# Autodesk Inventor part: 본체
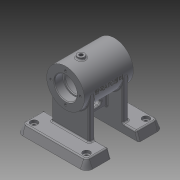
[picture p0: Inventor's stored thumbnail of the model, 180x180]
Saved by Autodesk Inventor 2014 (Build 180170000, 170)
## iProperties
Created: 2016-07
Part Number: 본체
Material: 일반
Document SubType Name: Modeling
Designer: USER
Density: 1 g/cm^3
Appearance: 기본값
Author: USER
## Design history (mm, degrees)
sketch "스케치1"
  geometry: L1 (0, 0)-(100, 0); L2 (100, 0)-(100, 110); L3 (100, 110)-(0, 110); L4 (0, 110)-(0, 0)
  constraints: 8 end point, 1 horizontal, 1 parallel, 1 perpendicular
  dimensions: "d0" = 100 distance of L1.start L1.end; "d1" = 110 distance of L1.end L2.end; "d2" = 100 distance of L2.end L3.end
extrude "돌출1" new body sketch "스케치1" distance "d3" = 12; taper "d4" = -20 deg
sketch "스케치2"
  geometry: L1 (4.368, 4.368)-(4.368, 105.632) reference; L2 (95.632, 105.632)-(95.632, 4.368) reference; L3 (4.368, 105.632)-(95.632, 105.632) reference; L4 (-24.368, 35)-(125.632, 35); L5 (125.632, 35)-(125.632, 75); L6 (125.632, 75)-(-24.368, 75); L7 (-24.368, 75)-(-24.368, 35); 3 further points
  constraints: 8 end point, 3 perpendicular, 2 midpoint, 1 horizontal alignment, 1 parallel
  dimensions: "d5" = 40 distance of L4.end L5.end; "d6" = 150 distance of L5.end L6.end; "d7" = 30 distance between parallel lines of L2 L5
extrude "돌출2" cut sketch "스케치2" distance "d8" = 12; taper "d9" = 0 deg
sketch "스케치3"
  geometry: L1 (95.632, 35)-(4.368, 35) reference; L2 (95.632, 4.368)-(4.368, 4.368) reference; L3 (4.368, 75)-(95.632, 75) reference; L4 (95.632, 105.632)-(95.632, 75) reference; L5 (4.368, 105.632)-(95.632, 105.632) reference; L6 (4.368, 75)-(4.368, 105.632) reference; L7 (23, 35)-(23, 27); L8 (23, 27)-(77, 27); L9 (77, 27)-(77, 35); L10 (23, 35)-(77, 35); L11 (23, 75)-(23, 83); L12 (23, 83)-(77, 83); L13 (77, 83)-(77, 75); L14 (23, 75)-(77, 75); 5 further points
  constraints: 16 end point, 4 midpoint, 4 perpendicular, 4 point on line, 2 collinear, 2 parallel, 2 vertical alignment
  dimensions: "d10" = 8 distance of L7.start L7.end; "d11" = 54 distance of L7.end L8.end; "d12" = 8 distance of L11.start L11.end; "d13" = 54 distance of L11.end L12.end
extrude "돌출3" join sketch "스케치3" distance "d14" = 58; taper "d15" = 0 deg
node "작업 평면1"
sketch "스케치4"
  geometry: L1 (-23, -12)-(-18.632, 0) reference; L2 (77, -12)-(-23, -12) reference; L3 (72.632, 0)-(77, -12) reference; L4 (54, 0)-(72.632, 0) reference; L5 (54, 0)-(54, 58) reference; L6 (0, 58)-(54, 58) reference; L7 (0, 0)-(0, 58) reference; L8 (-18.632, 0)-(0, 0) reference; C1 r 27 at (27, 58); 2 further points
  constraints: 2 coincident, 1 centre point, 1 midpoint
  dimensions: "d16" = 54 diameter of C1
extrude "돌출4" join sketch "스케치4" stored distance "d17" = 70; taper "d18" = 0 deg
node "작업 평면2"
sketch "스케치5"
  geometry: L1 (-85, -7)-(-31, -7) reference; L2 (-31, 63)-(-85, 63) reference; L3 (-58, 0)-(-58, 8) reference; L4 (-58, 8)-(-58, 8) reference; L5 (-58, 8)-(-58, 0) reference; L6 (-58, 0)-(-58, 0) reference; L7 (-58, 56)-(-58, 48) reference; L8 (-58, 48)-(-58, 48) reference; L9 (-58, 48)-(-58, 56) reference; L10 (-58, 56)-(-58, 56) reference; L11 (0, 0)-(0, 8) reference; L12 (0, 0)-(-58, 0) reference; L13 (-58, 8)-(-58, 0) reference; L14 (0, 8)-(-58, 8) reference; L15 (0, 48)-(0, 56) reference; L16 (0, 48)-(-58, 48) reference; L17 (-58, 56)-(-58, 48) reference; L18 (0, 56)-(-58, 56) reference; L19 (-85, 63)-(-85, -7) reference; L20 (-31, 63)-(-31, -7) reference; L21 (-10, 8)-(-10, 48); L22 (-58, 8)-(-10, 8); L23 (-58, 48)-(-10, 48); L24 (-58, 8)-(-58, 48); 1 further point
  constraints: 8 end point, 2 collinear, 2 perpendicular, 2 point on line
  dimensions: "d20" = 48 distance of L13.start L21.start
extrude "돌출5" join sketch "스케치5" stored distance "d21" = 8; taper "d22" = 0 deg
sketch "스케치6"
  geometry: L1 (31.298, 48)-(31.298, 8) reference; L2 (10, 48)-(10, 8) reference; L3 (20, 36)-(20, 20); L4 (16.5, 36)-(16.5, 20); L5 (23.5, 20)-(23.5, 36); L6 (-12, 8)-(-12, -27) reference; A1 r 3.5 centre (20, 36) between (23.5, 36) and (16.5, 36); A2 r 3.5 centre (20, 20) between (16.5, 20) and (23.5, 20); 2 further points
  constraints: 8 end point, 4 point on circle, 4 tangent, 2 centre point, 2 midpoint, 2 parallel, 1 horizontal alignment
  dimensions: "d23" = 3.5 radius of A2; "d24" = 23 dimension on A2 A1; "d25" = 32 distance from line of point (20, 28) L6
extrude "돌출6" cut sketch "스케치6" distance "d26" = 8; taper "d27" = 0 deg
sketch "스케치7"
  geometry: C1 r 27 at (0, 0) reference; C2 r 16 at (0, 0); 1 further point
  constraints: 1 centre point, 1 coincident
  dimensions: "d28" = 32 diameter of C2
extrude "돌출7" cut sketch "스케치7" distance "d29" = 12; taper "d30" = 0 deg
sketch "스케치8"
  geometry: C1 r 27 at (0, 0) reference; C2 r 16 at (0, 0); 1 further point
  constraints: 1 centre point, 1 coincident
  dimensions: "d31" = 32 diameter of C2
extrude "돌출8" cut sketch "스케치8" distance "d32" = 12; taper "d33" = 0 deg
node "작업 평면3"
sketch "스케치9"
  geometry: C1 r 16 at (0, 0) reference; C2 r 22 at (0, 0); 1 further point
  constraints: 1 centre point, 1 coincident
  dimensions: "d34" = 44 diameter of C2
extrude "돌출9" cut sketch "스케치9" stored distance "d35" = 42; taper "d36" = 0 deg
sketch "스케치10"
  geometry: C1 r 16 at (0, 0) reference; C2 r 14 at (0, 0); 1 further point
  constraints: 1 centre point, 1 coincident
  dimensions: "d37" = 28 diameter of C2
extrude "돌출10" cut sketch "스케치10" stored distance "d38" = 42; taper "d39" = 0 deg
node "작업 평면5"
  node "작업 평면4"
sketch "스케치11"
  geometry: L1 (4, -20)-(4, 20) reference; L2 (27, 20)-(4, 20) reference; L3 (27, 20)-(27, 28) reference; L4 (-27, 28)-(27, 28) reference; L5 (-27, 28)-(-27, 20) reference; L6 (-4, 20)-(-27, 20) reference; L7 (-4, 20)-(-4, -20) reference; L8 (-27, -20)-(-4, -20) reference; L9 (-27, -20)-(-27, -28) reference; L10 (27, -28)-(-27, -28) reference; L11 (27, -28)-(27, -20) reference; L12 (4, -20)-(27, -20) reference; L13 (-27, -35)-(27, -35) reference; L14 (27, 35)-(-27, 35) reference; C1 r 5 at (0, -13); 2 further points
  constraints: 1 centre point, 1 midpoint, 1 vertical alignment
  dimensions: "d41" = 10 diameter of C1; "d42" = 22 distance of point (0, -35) C1.centre
extrude "돌출11" join sketch "스케치11" stored distance "d43" = 42; taper "d44" = 0 deg
sketch "스케치12"
  geometry: C1 r 5 at (0, 0) reference; 2 further points
  constraints: 1 coincident
hole "구멍1" sketch "스케치12" at (0, 0) diameter "d45" = 5.188; stored, may be unused: countersink angle "d49" = 90 deg, drill point angle "d51" = 118 deg; dims "d46" = 10, "d47" = 4, "d48" = 2, "d50" = 10
sketch "스케치13"
  geometry: L1 (100, 75)-(0, 75) reference; L2 (0, 110)-(0, 75) reference; L3 (100, 110)-(0, 110) reference; L4 (100, 75)-(100, 110) reference; L5 (0, 35)-(0, 0) reference; L6 (0, 0)-(100, 0) reference; 4 further points
  constraints: 2 horizontal alignment, 2 vertical alignment
  dimensions: "d52" = 75 distance of point (87.5, 12.5) point (12.5, 12.5); "d53" = 85 distance of point (87.5, 12.5) point (87.5, 97.5); "d56" = 12.5 distance from line of point (12.5, 12.5) L5; "d57" = 12.5 distance from line of L6 point (12.5, 12.5)
hole "구멍2" sketch "스케치13" at (12.5, 97.5), (87.5, 97.5), (87.5, 12.5), (12.5, 12.5) diameter "d58" = 6; stored, may be unused: countersink angle "d62" = 90 deg, drill point angle "d64" = 118 deg; dims "d59" = 10, "d60" = 10, "d61" = 4, "d63" = 10
node "작업 평면6"
sketch "스케치14"
  geometry: L1 (0, 0)-(0, -27); L2 (0, 0)-(14.308, -22.897); C1 r 16 at (0, 0) reference; A1 r 27 centre (0, 0) between (4, -26.702) and (27, 0) reference; A2 r 27 centre (0, 0) between (-27, 0) and (27, 0) reference; A3 r 27 centre (0, 0) between (0, -27) and (14.308, -22.897) reference; 2 further points
  constraints: 4 end point, 4 point on circle, 1 coincident
  dimensions: "d66" = 32 deg angle of L1 L2
  node "투영된 루프9"
node "작업 평면7"
sketch "스케치17" dims "d77" = 42
  geometry: C1 r 16 at (0, 0) reference; C2 r 27 at (0, 0) reference; 3 further points
  constraints: 2 vertical alignment, 1 coincident, 2 other
hole "구멍4" sketch "스케치17" at (0, 21) diameter "d78" = 3.459; stored, may be unused: countersink angle "d82" = 90 deg, drill point angle "d84" = 118 deg; dims "d79" = 8, "d80" = 10, "d81" = 4, "d83" = 10
node "작업 평면8"
node "작업 평면9"
sketch "스케치18"
  geometry: L1 (35, 27)-(-35, 27) reference; L2 (35, -27)-(35, 27) reference; L3 (-35, 27)-(-35, -27) reference; L4 (35, -27)-(-35, -27) reference; 2 further points
  constraints: 1 other
  dimensions: "d88" = 27 distance from line of L1 point (0, 0); "d89" = 35 distance from line of L3 point (0, 0)
feature "엠보싱1" sketch "스케치18" dims "d0" = 100, "d1" = 110, "d2" = 100, "d90" = 0.5, "d91" = 0
node "작업 평면10"
sketch "스케치19"
  geometry: L1 (0, 0)-(0, -27); L2 (0, 0)-(-14.308, -22.897); C1 r 1.73 at (21, 0) reference; C2 r 1.73 at (0, -21) reference; C3 r 1.73 at (-21, 0) reference; C4 r 1.73 at (0, 21) reference; C5 r 16 at (0, 0) reference; A1 r 27 centre (0, 0) between (-14.308, -22.897) and (0, -27) reference; 2 further points
  constraints: 4 end point, 2 point on circle, 1 coincident, 1 vertical
  dimensions: "d92" = 32 deg angle of L1 L2
  node "투영된 루프12"
node "작업 평면11"
sketch "스케치20"
  geometry: L1 (-14.566, -21.692)-(-17.463, -21.692) reference; L2 (-17.463, -21.692)-(-17.463, -21.912) reference; L3 (-17.463, -21.912)-(-15.014, -21.912) reference; L4 (-15.014, -21.912)-(-15.014, -22.577) reference; L5 (-15.014, -22.577)-(-17.198, -22.577) reference; L6 (-17.198, -22.577)-(-17.198, -22.78) reference; L7 (-17.198, -22.78)-(-15.014, -22.78) reference; L8 (-15.014, -22.78)-(-15.014, -23.456) reference; L9 (-14.566, -23.651)-(-14.566, -21.692) reference; L10 (-9.803, -22.152)-(-10.834, -22.152) reference; L11 (-10.834, -22.152)-(-10.834, -21.265) reference; L12 (-10.834, -21.265)-(-11.208, -21.265) reference; L13 (-11.289, -21.41)-(-11.289, -23.615) reference; L14 (-11.289, -23.615)-(-10.834, -23.615) reference; L15 (-10.834, -23.615)-(-10.834, -22.348) reference; L16 (-10.834, -22.348)-(-9.803, -22.348) reference; L17 (-9.803, -22.348)-(-9.803, -22.152) reference; L18 (-8.67, -21.381)-(-9.071, -21.381) reference; L19 (0.488, -24.174)-(0.488, -21.793) reference; L20 (0.488, -21.793)-(2.042, -21.793) reference; L21 (2.042, -21.793)-(2.042, -21.546) reference; L22 (2.042, -21.546)-(-1.526, -21.546) reference; L23 (-1.526, -21.546)-(-1.526, -21.793) reference; L24 (-1.526, -21.793)-(0.034, -21.793) reference; L25 (0.034, -21.793)-(0.034, -24.174) reference; L26 (0.034, -24.174)-(0.488, -24.174) reference; L27 (4.878, -21.546)-(4.335, -21.546) reference; L28 (2.436, -24.174)-(2.917, -24.174) reference; L29 (3.474, -23.456)-(5.726, -23.456) reference; L30 (6.296, -24.174)-(6.777, -24.174) reference; L31 (18.853, -21.307)-(17.374, -21.307) reference; L32 (17.374, -21.307)-(17.374, -21.521) reference; L33 (17.374, -21.521)-(18.853, -21.521) reference; L34 (18.853, -21.521)-(18.853, -21.307) reference; L35 (15.061, -21.332)-(15.061, -22.547) reference; L36 (15.061, -22.547)-(13.942, -22.547) reference; L37 (13.942, -22.547)-(13.942, -22.761) reference; L38 (13.942, -22.761)-(15.061, -22.761) reference; L39 (15.061, -22.761)-(15.061, -23.651) reference; L40 (15.061, -23.651)-(15.536, -23.651) reference; L41 (15.536, -23.651)-(15.536, -21.168) reference; L42 (15.536, -21.168)-(15.231, -21.168) reference; L43 (18.731, -23.612)-(18.731, -24.095) reference; L44 (18.731, -24.095)-(14.844, -24.095) reference; L45 (14.844, -24.095)-(14.844, -24.264) reference; L46 (14.844, -24.264)-(19.193, -24.264) reference; L47 (19.193, -24.264)-(19.193, -23.506) reference; L48 (19.193, -23.506)-(18.84, -23.506) reference; L49 (20.047, -21.793)-(16.282, -21.793) reference; L50 (16.282, -21.793)-(16.282, -21.999) reference; L51 (16.282, -21.999)-(20.047, -21.999) reference; L52 (20.047, -21.999)-(20.047, -21.793) reference; L53 (13.311, -22.495)-(8.942, -22.495) reference; L54 (8.657, -21.53)-(12.463, -21.53) reference; L55 (12.463, -21.53)-(12.463, -21.298) reference; L56 (12.463, -21.298)-(8.175, -21.298) reference; L57 (8.446, -22.495)-(7.307, -22.495) reference; L58 (7.307, -22.495)-(7.307, -22.699) reference; L59 (7.307, -22.699)-(10.095, -22.699) reference; L60 (10.095, -22.699)-(10.095, -23.337) reference; L61 (10.095, -23.337)-(8.284, -23.337) reference; L62 (8.284, -23.337)-(8.284, -24.332) reference; L63 (8.284, -24.332)-(8.745, -24.332) reference; L64 (8.745, -24.332)-(8.745, -23.522) reference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; C1 r 6 at (0, 0); 63 further points
  constraints: 2 midpoint, 1 centre point, 1 horizontal alignment, 1 vertical alignment, 76 other
  dimensions: "d93" = 12 diameter of C1
extrude "돌출13" join sketch "스케치20" stored distance "d94" = 6; taper "d95" = 0 deg
sketch "스케치21"
  geometry: C1 r 6 at (0, 0) reference; 2 further points
  constraints: 1 coincident
hole "구멍5" sketch "스케치21" at (0, 0) diameter "d96" = 5.188; stored, may be unused: countersink angle "d100" = 90 deg, drill point angle "d102" = 118 deg; dims "d97" = 10, "d98" = 10, "d99" = 4, "d101" = 10
fillet "모깎기1" dims "d103" = 10, "d104" = 5, "d105" = 10, "d106" = 5, "d107" = 10, "d108" = 5, "d109" = 10, "d110" = 5
fillet "모깎기2" dims "d111" = 2
chamfer "모따기1" distance "d112" = 1; stored, may be unused: second distance "d113" = 2, angle "d114" = 45 deg
fillet "모깎기3" dims "d115" = 3
node "솔리드1"
pattern_circular "원형 패턴1" dims angle "d86" = 360 deg
mirror "대칭1"
node "투영된 루프1"
node "투영된 루프2"
node "투영된 루프3"
node "투영된 루프4"
node "투영된 루프5"
node "투영된 루프6"
node "투영된 루프7"
node "투영된 루프8"
node "투영된 루프13"
other parameters: "d40" = 3
